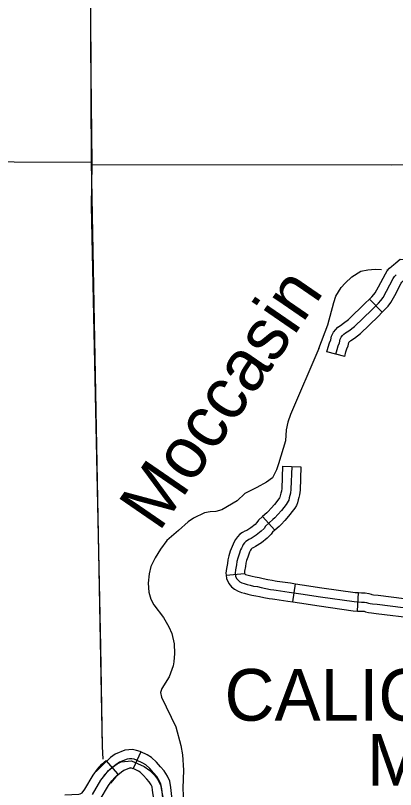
# Model space of a CAD drawing. Extents: x 1377389 to 1380723, y 1168351 to 1170484.
# Drawn here: x 1378554.8 to 1378616.9, y 1169324.4 to 1169450.8 of the extents above; entities that cross this region are included whole.
import ezdxf

# ---------------------------------------------------------------- set-up
doc = ezdxf.new("R2010")
doc.units = 0
doc.layers.add('B_Fill', color=7, linetype='Continuous')

msp = doc.modelspace()

# ---------------------------------------------------------------- linework, layer by layer
at = {"layer": 'B_Fill'}
for p, q in [((1378614.74, 1169402.35), (1378612.64, 1169404.49)), ((1378608.61, 1169395.14), (1378605.71, 1169395.91)), ((1378598.45, 1169377.19), (1378601.45, 1169377.11)), ((1378595.2, 1169368.99), (1378597.21, 1169366.76)), ((1378589.25, 1169359.43), (1378592.24, 1169359.68)), ((1378600.12, 1169355.04), (1378600.57, 1169358.01)), ((1378610.72, 1169353.55), (1378610.88, 1169356.55)), ((1378575.33, 1169330.52), (1378574.04, 1169327.81)), ((1378571.63, 1169326.89), (1378569.64, 1169329.14))]:
    msp.add_line(p, q, dxfattribs=at)
for points in [[(1378569.15, 1169329.36), (1378569.05, 1169331.4), (1378568.77, 1169347.73), (1378567.25, 1169419.74), (1378567.36, 1169426.5), (1378567.35, 1169426.64), (1378567.19, 1169441.35), (1378566.77, 1169525.05)], [(1378569.08, 1169331.33), (1378567.27, 1169426.87), (1378566.75, 1169523.96)], [(1378516.74, 1169427.09), (1378567.27, 1169426.87)], [(1378567.36, 1169426.5), (1378616.22, 1169426.46), (1378671.81, 1169426.6)], [(1378612.64, 1169404.49), (1378613.03, 1169404.87), (1378613.37, 1169405.25), (1378613.61, 1169405.56), (1378614.13, 1169406.54), (1378615.25, 1169408.63), (1378615.56, 1169409.12), (1378615.94, 1169409.54), (1378616.31, 1169409.9), (1378616.57, 1169410.1), (1378616.97, 1169410.44), (1378617.67, 1169411.03), (1378618.78, 1169410.99), (1378619.54, 1169410.85), (1378620.2, 1169410.74), (1378620.68, 1169410.63), (1378621.13, 1169410.5), (1378621.41, 1169410.43)], [(1378604.41, 1169396.43), (1378605.87, 1169400.28), (1378606.84, 1169403.97), (1378607.17, 1169404.98), (1378608.06, 1169406.4), (1378608.68, 1169407.13), (1378609.77, 1169408.12), (1378611.25, 1169409.08), (1378612.38, 1169409.3), (1378613.58, 1169409.39), (1378614.64, 1169409.35)], [(1378607.16, 1169395.52), (1378607.36, 1169396.28), (1378607.54, 1169396.9), (1378607.74, 1169397.38), (1378607.89, 1169397.94), (1378608.05, 1169398.29), (1378608.27, 1169398.56), (1378608.49, 1169398.8), (1378608.75, 1169398.98), (1378609.31, 1169399.35), (1378610.19, 1169400.04), (1378613.02, 1169402.76), (1378614.11, 1169403.83), (1378614.53, 1169404.29), (1378614.88, 1169404.75), (1378615.45, 1169405.83), (1378616.54, 1169407.87), (1378616.76, 1169408.21), (1378617.01, 1169408.49)], [(1378615.51, 1169409.31), (1378615.63, 1169409.3), (1378615.61, 1169409.18)], [(1378614.74, 1169402.35), (1378615.19, 1169402.79), (1378615.69, 1169403.34), (1378616.14, 1169403.94), (1378616.78, 1169405.12), (1378617.84, 1169407.11), (1378617.95, 1169407.29), (1378618.09, 1169407.44), (1378618.3, 1169407.65), (1378618.48, 1169407.79), (1378618.68, 1169407.96), (1378619.02, 1169407.9), (1378619.6, 1169407.8), (1378619.93, 1169407.72), (1378620.34, 1169407.61), (1378620.65, 1169407.52)], [(1378605.71, 1169395.91), (1378605.91, 1169396.67), (1378606.12, 1169397.39), (1378606.32, 1169397.87), (1378606.48, 1169398.44), (1378606.76, 1169399.09), (1378607.14, 1169399.54), (1378607.5, 1169399.95), (1378607.92, 1169400.22), (1378608.43, 1169400.57), (1378609.21, 1169401.18), (1378611.98, 1169403.84), (1378612.64, 1169404.49)], [(1378608.61, 1169395.14), (1378608.81, 1169395.88), (1378608.96, 1169396.4), (1378609.16, 1169396.9), (1378609.31, 1169397.43), (1378609.34, 1169397.5), (1378609.4, 1169397.57), (1378609.48, 1169397.66), (1378609.59, 1169397.73), (1378610.19, 1169398.14), (1378611.18, 1169398.9), (1378614.07, 1169401.69), (1378614.74, 1169402.35)], [(1378604.41, 1169396.43), (1378599.75, 1169385.64), (1378599.3, 1169384.39), (1378599.07, 1169383.14), (1378598.95, 1169381.38), (1378597.78, 1169377.61), (1378597.45, 1169376.6), (1378596.81, 1169375.31), (1378595.82, 1169374.61), (1378594.27, 1169373.75), (1378592.32, 1169372.74), (1378591.03, 1169371.57), (1378588.56, 1169370.1), (1378587.59, 1169369.79), (1378586.64, 1169369.75), (1378585.74, 1169369.59), (1378583.9, 1169368.7)], [(1378599.95, 1169377.15), (1378599.84, 1169373.44), (1378599.74, 1169372.83), (1378599.64, 1169372.42), (1378599.55, 1169372.03), (1378599.47, 1169371.68), (1378599.4, 1169371.49), (1378599.22, 1169371.21), (1378599.05, 1169370.97), (1378598.29, 1169369.99), (1378597.71, 1169369.33), (1378597.19, 1169368.76), (1378596.9, 1169368.5), (1378595.67, 1169367.39), (1378595.44, 1169367.03), (1378594.96, 1169366.57), (1378594.16, 1169365.93), (1378593.35, 1169365.4), (1378592.98, 1169365.24), (1378592.73, 1169365.08), (1378592.44, 1169364.91), (1378592.24, 1169364.7), (1378592.05, 1169364.44), (1378591.92, 1169364.17), (1378591.73, 1169363.8), (1378591.61, 1169363.54), (1378591.35, 1169362.83), (1378591.14, 1169362.18), (1378591.02, 1169361.64), (1378590.94, 1169361.1), (1378590.79, 1169360.28), (1378590.73, 1169359.74), (1378590.77, 1169359.24), (1378590.94, 1169358.86), (1378591.19, 1169358.59), (1378591.48, 1169358.34), (1378591.81, 1169358.15), (1378592.19, 1169358.03), (1378592.67, 1169357.88), (1378593.15, 1169357.76), (1378593.71, 1169357.63), (1378594.36, 1169357.53), (1378594.98, 1169357.4), (1378595.73, 1169357.24), (1378596.5, 1169357.09), (1378597.05, 1169357.01), (1378597.4, 1169356.96), (1378599.53, 1169356.65), (1378601.45, 1169356.36), (1378604.64, 1169355.88), (1378610.16, 1169355.09), (1378611.33, 1169355.02), (1378611.83, 1169355.02), (1378612.16, 1169354.96), (1378612.48, 1169354.86), (1378612.77, 1169354.77), (1378613.14, 1169354.73), (1378613.92, 1169354.65), (1378620.3, 1169353.86)], [(1378598.45, 1169377.19), (1378598.35, 1169373.58), (1378598.27, 1169373.14), (1378598.18, 1169372.78), (1378598.09, 1169372.37), (1378598.04, 1169372.15), (1378597.98, 1169372.06), (1378597.84, 1169371.86), (1378597.13, 1169370.94), (1378596.6, 1169370.33), (1378596.13, 1169369.82), (1378595.9, 1169369.61), (1378595.2, 1169368.99)], [(1378601.45, 1169377.11), (1378601.34, 1169373.3), (1378601.21, 1169372.52), (1378601.1, 1169372.07), (1378601.01, 1169371.69), (1378600.91, 1169371.25), (1378600.74, 1169370.8), (1378600.45, 1169370.36), (1378600.25, 1169370.08), (1378599.45, 1169369.03), (1378598.83, 1169368.33), (1378598.25, 1169367.69), (1378597.9, 1169367.38), (1378597.21, 1169366.76)], [(1378583.9, 1169368.7), (1378583.02, 1169368.1), (1378581.48, 1169366.71), (1378579.57, 1169365.06), (1378578.5, 1169363.64), (1378577.64, 1169362.22), (1378576.97, 1169360.8), (1378576.66, 1169359.62), (1378576.51, 1169358.09), (1378576.64, 1169356.65), (1378576.97, 1169355.48), (1378577.43, 1169354.57), (1378578.99, 1169352.5), (1378579.9, 1169350.98), (1378580.37, 1169349.87), (1378580.76, 1169348.2), (1378580.8, 1169346.6), (1378580.71, 1169345.25), (1378580.57, 1169344.57), (1378579.95, 1169342.79), (1378578.75, 1169340.89), (1378578.53, 1169340.26), (1378578.69, 1169339.46), (1378581.01, 1169334.65), (1378581.86, 1169331.59), (1378582.11, 1169330.03), (1378582.27, 1169327.53), (1378582.17, 1169324.61), (1378582.35, 1169320.99)], [(1378595.2, 1169368.99), (1378594.52, 1169368.37), (1378594.27, 1169367.99), (1378593.97, 1169367.69), (1378593.28, 1169367.14), (1378592.65, 1169366.73), (1378592.29, 1169366.58), (1378591.94, 1169366.36), (1378591.49, 1169366.08), (1378591.08, 1169365.66), (1378590.76, 1169365.21), (1378590.58, 1169364.84), (1378590.37, 1169364.45), (1378590.22, 1169364.1), (1378589.93, 1169363.32), (1378589.7, 1169362.58), (1378589.54, 1169361.92), (1378589.46, 1169361.34), (1378589.31, 1169360.5), (1378589.22, 1169359.76), (1378589.25, 1169359.43)], [(1378597.21, 1169366.76), (1378596.82, 1169366.41), (1378596.61, 1169366.08), (1378595.95, 1169365.44), (1378595.04, 1169364.71), (1378594.06, 1169364.07), (1378593.67, 1169363.9), (1378593.52, 1169363.81), (1378593.39, 1169363.73), (1378593.34, 1169363.66), (1378593.25, 1169363.49), (1378593.08, 1169363.15), (1378593.01, 1169362.98), (1378592.77, 1169362.34), (1378592.59, 1169361.78), (1378592.49, 1169361.36), (1378592.42, 1169360.85), (1378592.27, 1169360.06), (1378592.23, 1169359.72), (1378592.24, 1169359.68)], [(1378589.25, 1169359.43), (1378589.3, 1169358.86), (1378589.67, 1169358.03), (1378590.14, 1169357.51), (1378590.61, 1169357.11), (1378591.2, 1169356.78), (1378591.73, 1169356.6), (1378592.26, 1169356.44), (1378592.79, 1169356.3), (1378593.43, 1169356.16), (1378594.09, 1169356.05), (1378594.67, 1169355.94), (1378595.43, 1169355.77), (1378596.25, 1169355.61), (1378596.84, 1169355.52), (1378597.2, 1169355.48), (1378599.3, 1169355.17), (1378600.12, 1169355.04)], [(1378592.24, 1169359.68), (1378592.24, 1169359.67), (1378592.34, 1169359.58), (1378592.42, 1169359.53), (1378592.64, 1169359.46), (1378593.07, 1169359.33), (1378593.5, 1169359.22), (1378593.99, 1169359.11), (1378594.62, 1169359), (1378595.29, 1169358.87), (1378596.03, 1169358.71), (1378596.76, 1169358.57), (1378597.25, 1169358.49), (1378597.6, 1169358.45), (1378599.75, 1169358.14), (1378600.57, 1169358.01)], [(1378600.57, 1169358.01), (1378601.67, 1169357.84), (1378604.85, 1169357.36), (1378610.31, 1169356.58), (1378610.88, 1169356.55)], [(1378610.88, 1169356.55), (1378611.37, 1169356.52), (1378611.97, 1169356.52), (1378612.54, 1169356.42), (1378612.92, 1169356.29), (1378613.06, 1169356.25), (1378613.31, 1169356.22), (1378614.09, 1169356.14), (1378620.46, 1169355.35), (1378621.08, 1169355.29), (1378621.88, 1169355), (1378622.03, 1169354.91)], [(1378600.12, 1169355.04), (1378601.22, 1169354.88), (1378604.42, 1169354.4), (1378610.01, 1169353.59), (1378610.72, 1169353.55)], [(1378610.72, 1169353.55), (1378611.29, 1169353.52), (1378611.69, 1169353.52), (1378611.79, 1169353.51), (1378612.03, 1169353.42), (1378612.48, 1169353.3), (1378612.98, 1169353.24), (1378613.74, 1169353.16), (1378620.14, 1169352.36), (1378620.43, 1169352.34), (1378620.55, 1169352.29), (1378620.44, 1169352.36)], [(1378575.33, 1169330.52), (1378575.18, 1169330.59), (1378574.6, 1169330.77), (1378573.98, 1169330.92), (1378573.33, 1169330.89), (1378572.69, 1169330.81), (1378571.12, 1169330.16), (1378570.35, 1169329.64), (1378569.14, 1169328.48), (1378568.04, 1169327.34)], [(1378580.72, 1169320.54), (1378580.61, 1169321.79), (1378580.4, 1169323.25), (1378580.2, 1169324.73), (1378580.03, 1169325.74), (1378579.65, 1169326.56), (1378579.11, 1169327.44), (1378578.53, 1169328.08), (1378577.88, 1169328.84), (1378577.05, 1169329.61), (1378576.36, 1169330.03), (1378575.33, 1169330.52)], [(1378562.9, 1169323.52), (1378565.18, 1169323.61), (1378565.41, 1169323.66), (1378565.72, 1169323.83), (1378566.16, 1169324.43), (1378567.52, 1169326.74), (1378568.26, 1169327.71), (1378568.97, 1169328.55), (1378569.64, 1169329.14)], [(1378567.44, 1169323.59), (1378568.79, 1169325.89), (1378569.45, 1169326.75), (1378570.06, 1169327.47), (1378570.86, 1169328.17), (1378571.47, 1169328.61), (1378572.1, 1169328.89), (1378573.79, 1169329.1), (1378575.87, 1169328.14), (1378576.79, 1169327.5), (1378577.55, 1169326.76), (1378578.03, 1169326.09), (1378578.51, 1169325.13), (1378579.52, 1169319.93)], [(1378578.92, 1169323.04), (1378578.72, 1169324.51), (1378578.59, 1169325.3), (1378578.33, 1169325.84), (1378577.91, 1169326.53), (1378577.4, 1169327.09), (1378576.79, 1169327.8), (1378576.14, 1169328.4), (1378575.64, 1169328.71), (1378574.63, 1169329.19), (1378574.2, 1169329.33), (1378573.84, 1169329.41), (1378573.46, 1169329.4), (1378573.08, 1169329.35), (1378571.83, 1169328.83), (1378571.25, 1169328.44), (1378570.21, 1169327.58), (1378569.27, 1169326.67)], [(1378574.07, 1169327.79), (1378573.79, 1169327.88), (1378573.7, 1169327.91), (1378573.6, 1169327.9), (1378573.48, 1169327.88), (1378572.55, 1169327.5), (1378572.15, 1169327.23), (1378571.21, 1169326.46), (1378570.35, 1169325.43)], [(1378577.73, 1169320.28), (1378577.63, 1169321.45), (1378577.43, 1169322.83), (1378577.23, 1169324.28), (1378577.14, 1169324.85), (1378577.01, 1169325.13), (1378576.7, 1169325.63), (1378576.28, 1169326.1), (1378575.71, 1169326.75), (1378575.23, 1169327.2), (1378574.92, 1169327.39), (1378574.04, 1169327.81)], [(1378563.03, 1169320.52), (1378565.54, 1169320.62), (1378566.45, 1169320.81), (1378567.74, 1169321.52), (1378568.67, 1169322.78), (1378570.02, 1169325.07), (1378570.59, 1169325.83), (1378571.11, 1169326.43), (1378571.63, 1169326.89)]]:
    msp.add_lwpolyline(points, dxfattribs=at)

# ---------------------------------------------------------------- texts
msp.add_text('Moccasin', height=8.448, rotation=55.5069, dxfattribs=at).set_placement((1378578.28, 1169366.34))
for s, p in [('CALICO ROCK', (1378588.99, 1169335.63)), ('MUNICIPAL', (1378612.23, 1169325))]:
    msp.add_text(s, height=8.448, dxfattribs=at).set_placement(p)

doc.saveas('drawing.dxf')
